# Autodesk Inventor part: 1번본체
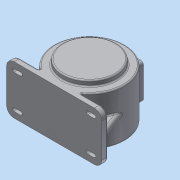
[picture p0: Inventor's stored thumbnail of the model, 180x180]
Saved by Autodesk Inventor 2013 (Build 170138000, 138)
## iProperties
Created: 2015-06
Part Number: 1번본체
Material: 알루미늄 6061
Document SubType Name: Modeling
Designer: dgall
Density: 2.71 g/cm^3
Mass: 3298.17 g
Surface Area: 2321.9 cm^2
Volume: 1217.04 cm^3
Author: dgall
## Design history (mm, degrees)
sketch "스케치1"
  geometry: L1 (0, 59)-(0, -59); L2 (0, 59)-(85, 59); L3 (85, 59)-(85, -59); L4 (85, -59)-(0, -59); L5 (0, 51)-(77, 51); L6 (77, 51)-(77, -51); L7 (77, -51)-(0, -51); 2 further points
  constraints: 14 end point, 4 perpendicular, 2 coincident, 2 parallel, 2 point on line, 1 midpoint, 1 vertical
  dimensions: "d0" = 118 distance of L1.start L1.end; "d2" = 170 diameter of L3 L1; "d3" = 154 diameter of L6 L1; "d4" = 8 distance between parallel lines of L5 L2; "d5" = 8 distance between parallel lines of L4 L7 (= d4)
revolve "회전1" sketch "스케치1" stored, may be unused: angle "d6" = 90 deg
sketch "스케치2"
  geometry: C1 r 85 at (0, 0) reference; C2 r 65 at (0, 0)
  constraints: 1 centre point, 1 coincident
  dimensions: "d7" = 130 diameter of C2
extrude "돌출1" join sketch "스케치2" distance "d9" = 3; taper "d10" = 0 deg
sketch "스케치3"
  geometry: C1 r 85 at (0, 0) reference; C2 r 65 at (0, 0)
  constraints: 1 centre point, 1 coincident
  dimensions: "d11" = 130 diameter of C2
extrude "돌출2" join sketch "스케치3" distance "d13" = 13; taper "d14" = 0 deg
sketch "스케치4"
  geometry: L1 (115, -71)-(115, -85); L2 (115, -85)-(-115, -85); L3 (-115, -85)-(-115, -71); L4 (-115, -71)-(-46.733, -71); L5 (46.733, -71)-(115, -71); C1 r 65 at (0, 0) reference; A1 r 85 centre (0, 0) between (-46.733, -71) and (46.733, -71) reference
  constraints: 10 end point, 3 parallel, 2 horizontal, 2 perpendicular, 2 point on circle, 1 collinear, 1 horizontal alignment
  dimensions: "d15" = 14 distance of L2.end L3.end; "d17" = 85 distance from line of L2 C1.centre; "d18" = 230 distance of L1.end L2.end
extrude "돌출3" join sketch "스케치4" distance "d19" = 118; taper "d20" = 0 deg
node "작업 평면1"
sketch "스케치5"
  geometry: L1 (-157.5, 101.5)-(-72.5, 101.5); L2 (-72.5, 101.5)-(-72.5, 16.5); L3 (-72.5, 16.5)-(-157.5, 16.5); L4 (-157.5, 16.5)-(-157.5, 101.5); L5 (0, 118)-(-230, 118) reference; L6 (-230, 0)-(-230, 118) reference; 3 further points
  constraints: 8 end point, 2 midpoint, 2 parallel, 1 horizontal, 1 horizontal alignment, 1 perpendicular, 1 vertical alignment
  dimensions: "d22" = 85 distance of L1.start L1.end; "d24" = 85 distance of L3.end L1.start
extrude "돌출4" join sketch "스케치5" stored distance "d25" = 118; taper "d26" = 0 deg
hole "구멍1" diameter "d29" = 95; stored, may be unused: countersink angle "d33" = 90 deg, drill point angle "d35" = 0 deg; dims "d27" = 10, "d28" = 10, "d30" = 6, "d31" = 4, "d32" = 2, "d34" = 11
sketch "스케치6"
  geometry: C1 r 77 at (0, 0) reference; C2 r 31 at (0, 0)
  constraints: 1 centre point, 1 coincident
  dimensions: "d36" = 62 diameter of C2
extrude "돌출5" join sketch "스케치6" distance "d38" = 3.5; taper "d39" = -25 deg
hole "구멍2" diameter "d42" = 30; stored, may be unused: countersink angle "d46" = 90 deg, drill point angle "d48" = 0 deg; dims "d40" = 10, "d41" = 10, "d43" = 6, "d44" = 47, "d45" = 14, "d47" = 17
fillet "모깎기1" dims "d58" = 7
fillet "모깎기2" dims "d59" = 18
node "작업 평면2"
sketch "스케치7"
  geometry: L1 (-97, -71)-(-46.733, -71) reference; L2 (-115, -71)-(-97, -71) reference; L3 (-84.87, -4.703)-(-109, -71); A1 r 85 centre (0, 0) between (46.733, -71) and (-46.733, -71) reference; 1 further point
  constraints: 2 end point, 1 point on circle, 1 point on line
  dimensions: "d61" = 110 deg angle of L2 L3; "d62" = 6 distance of L3.end L2.start
feature "리브1" sketch "스케치7" dims "d63" = 1, "d64" = 15, "d65" = 0, "d66" = 0, "d67" = 1, "d68" = 1
fillet "모깎기3" dims "d69" = 7.5
sketch "스케치8"
  geometry: C1 r 47.5 at (0, 0) reference; 1 further point
  constraints: 1 vertical alignment
  dimensions: "d70" = 55 distance of C1.centre point (0, 55)
sketch "스케치10"
  geometry: L1 (-93.467, -66.5)-(-147.752, -66.5) reference; L2 (-147.752, -51.5)-(-93.467, -51.5) reference; L3 (-93.467, 0)-(-93.467, -51.5) reference; L4 (-143.733, 0)-(-93.467, 0) reference; L5 (-161.733, -18)-(-161.733, -100) reference; L6 (-93.467, -118)-(-143.733, -118) reference; L7 (-93.467, -66.5)-(-93.467, -118) reference; L8 (-127.733, -109)-(-143.733, -109); L9 (-143.733, -91)-(-127.733, -91); L10 (-143.733, -104)-(-127.733, -104); L11 (-127.733, -96)-(-143.733, -96); A1 r 18 centre (-143.733, -18) between (-143.733, 0) and (-161.733, -18) reference; A2 r 18 centre (-143.733, -100) between (-161.733, -100) and (-143.733, -118) reference; A3 r 9 centre (-143.733, -100) between (-143.733, -91) and (-143.733, -109); A4 r 9 centre (-127.733, -100) between (-127.733, -109) and (-127.733, -91); A5 r 4 centre (-127.733, -100) between (-127.733, -104) and (-127.733, -96); A6 r 4 centre (-143.733, -100) between (-143.733, -96) and (-143.733, -104); 2 further points; 1 other entity
  constraints: 8 end point, 8 point on circle, 4 centre point, 4 tangent, 2 parallel, 1 coincident, 1 horizontal alignment, 1 perpendicular, 4 other
  dimensions: "d78" = 16 distance of A2.centre A4.centre; "d79" = 18 distance between parallel lines of L9 L8; "d80" = 8 distance between parallel lines of L11 L10
  node "투영된 루프1"
extrude "돌출6" join sketch "스케치10" distance "d81" = 3; taper "d82" = 0 deg
extrude "돌출7" cut sketch "스케치10" stored distance "d83" = 30; taper "d84" = 0 deg
node "작업 평면4"
  node "작업 평면3"
sketch "스케치11"
  geometry: 2 further points
  constraints: 1 coincident, 1 other
feature "엠보싱1" sketch "스케치11" dims "d86" = 0.5, "d87" = 0
hole "구멍5" sketch "스케치8" diameter "d88" = 3.242; stored, may be unused: countersink angle "d92" = 90 deg, drill point angle "d94" = 0 deg; dims "d89" = 10, "d90" = 47, "d91" = 14, "d93" = 11
chamfer "모따기1" distance "d99" = 1; stored, may be unused: second distance "d100" = 2, angle "d101" = 45 deg
chamfer "모따기2" distance "d102" = 1; stored, may be unused: second distance "d103" = 2, angle "d104" = 45 deg
fillet "모깎기5" dims "d105" = 0.3
fillet "모깎기6" dims "d106" = 3
fillet "모깎기7" dims "d107" = 3
fillet "모깎기8" dims "d111" = 2
fillet "모깎기9" dims "d112" = 3
sketch "스케치12"
  geometry: L1 (80.522, 42.5)-(91, 42.5) reference; L2 (91, 42.5)-(91, 35.5) reference; L3 (91, -42.5)-(80.522, -42.5) reference; L4 (88, 42.5)-(88, -42.5); L5 (-85, -45)-(-85, -37) reference; L6 (91, 35.5)-(91, -35.5) reference; L7 (91, -35.5)-(91, -42.5) reference; 1 further point
  constraints: 2 end point, 2 point on line, 1 perpendicular
  dimensions: "d113" = 173 distance between parallel lines of L5 L4
extrude "돌출8" cut sketch "스케치12" stored distance "d114" = 10; taper "d115" = 0 deg
hole "구멍6" diameter "d118" = 70; stored, may be unused: countersink angle "d122" = 90 deg, drill point angle "d124" = 0 deg; dims "d116" = 42.5, "d117" = 42.5, "d119" = 6, "d120" = 4, "d121" = 2, "d123" = 8
sketch "스케치13"
  geometry: A1 r 7 centre (0, 7) between (-7, 7) and (0, 0) reference; A2 r 7 centre (71, 7) between (71, 0) and (78, 7) reference; A3 r 7 centre (71, 78) between (78, 78) and (71, 85) reference; A4 r 7 centre (0, 78) between (0, 85) and (-7, 78) reference
hole "구멍7" sketch "스케치13" at (0, 7), (71, 7), (71, 78), (0, 78) diameter "d125" = 3.242; stored, may be unused: countersink angle "d129" = 90 deg, drill point angle "d131" = 118 deg; dims "d126" = 10, "d127" = 4, "d128" = 2, "d130" = 13
chamfer "모따기4" distance "d132" = 1; stored, may be unused: second distance "d133" = 2, angle "d134" = 45 deg
node "솔리드1"
mirror "대칭1"
mirror "대칭2"
mirror "대칭3"
pattern_circular "원형 패턴1" dims angle "d96" = 360 deg
node "작업축1"
other parameters: "d21" = -176, "d60" = -59, "d85" = -65 deg
